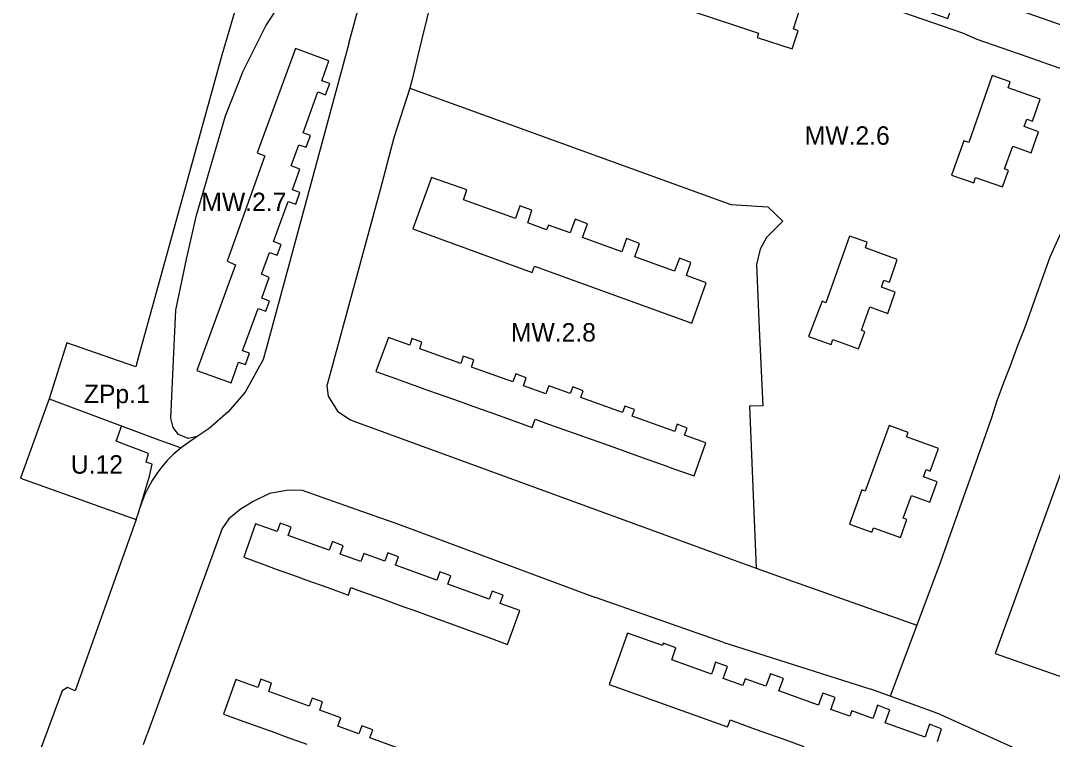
# Model space of a CAD drawing. Extents: x 7428239 to 7429836, y 5549133 to 5550853.
# Drawn here: x 7429036.9 to 7429316.4, y 5550071.7 to 5550266.4 of the extents above; entities that cross this region are included whole.
import ezdxf

# ---------------------------------------------------------------- set-up
doc = ezdxf.new("R2010")
doc.units = 0
for name, color, linetype in [('LIN_linie rozgraniczające', 7, 'Continuous'), ('LIN_nieprzekraczalna linia zabudowy', 7, 'Continuous'), ('LIN_obowiązująca linia zabudowy', 7, 'Continuous'), ('TXT_Oznaczenia Przeznaczenia', 7, 'Continuous')]:
    doc.layers.add(name, color=color, linetype=linetype)

msp = doc.modelspace()

# ---------------------------------------------------------------- linework, layer by layer
at = {"layer": 'LIN_linie rozgraniczające'}
for p, q in [((7429100.94, 5550289.63), (7429091.4, 5550257.09)), ((7429091.4, 5550257.09), (7429068.97, 5550176.06)), ((7429142.32, 5550248.09), (7429137.96, 5550234.67)), ((7429049.35, 5550179.1), (7429044.54, 5550163.96)), ((7429059.24, 5550175.67), (7429049.35, 5550179.1)), ((7429068.02, 5550172.62), (7429059.24, 5550175.67)), ((7429068.97, 5550176.06), (7429068.02, 5550172.62)), ((7429119.83, 5550167.51), (7429120.18, 5550164.65)), ((7429044.54, 5550163.96), (7429043.58, 5550161.27)), ((7429044.54, 5550163.96), (7429073.32, 5550153.2)), ((7429120.18, 5550164.65), (7429122.67, 5550160.56)), ((7429043.58, 5550161.27), (7429036.85, 5550142.43)), ((7429122.67, 5550160.56), (7429126.01, 5550158.31)), ((7429126.01, 5550158.31), (7429127.14, 5550157.89)), ((7429127.14, 5550157.89), (7429230.23, 5550120.21)), ((7429319.78, 5550146.91), (7429300.94, 5550094.93)), ((7429036.85, 5550142.43), (7429064.12, 5550132.66)), ((7429109.41, 5550139.17), (7429104.25, 5550138.25)), ((7429113.23, 5550139.13), (7429109.41, 5550139.17)), ((7429064.12, 5550132.66), (7429068.15, 5550131.21)), ((7429068.15, 5550131.21), (7429068.8, 5550133.04)), ((7429068.8, 5550133.04), (7429069.27, 5550134.6)), ((7429068.15, 5550131.21), (7429051.62, 5550084.84)), ((7429091.47, 5550128.81), (7429085.27, 5550111.76)), ((7429230.23, 5550120.21), (7429236.11, 5550118.05)), ((7429236.11, 5550118.05), (7429244.71, 5550115.01)), ((7429192.45, 5550110.13), (7429183.94, 5550113.3)), ((7429085.27, 5550111.76), (7429071.18, 5550073.05)), ((7429192.59, 5550110.07), (7429192.45, 5550110.13)), ((7429227.15, 5550097.97), (7429192.59, 5550110.07)), ((7429279.68, 5550102.63), (7429272.45, 5550083.41)), ((7429300.94, 5550094.93), (7429354.94, 5550075.82)), ((7429048.11, 5550084.81), (7429042.17, 5550068.75)), ((7429049.58, 5550085.76), (7429048.11, 5550084.81)), ((7429051.62, 5550084.84), (7429049.58, 5550085.76)), ((7429070.18, 5550070.29), (7429071.18, 5550073.05))]:
    msp.add_line(p, q, dxfattribs=at)
for points in [[(7429125.74, 5550260.21), (7429103.38, 5550177.46), (7429102.6, 5550174.57), (7429099.05, 5550168.16), (7429097.72, 5550165.74), (7429093.08, 5550160.45), (7429087.93, 5550155.92), (7429084.71, 5550153.7), (7429082.25, 5550153.23), (7429079.64, 5550154.26), (7429078.14, 5550156.16), (7429077.55, 5550158.71), (7429078.38, 5550176.44), (7429078.93, 5550187.93), (7429081.75, 5550201.8), (7429084.47, 5550213.72), (7429092.38, 5550240.66), (7429097.19, 5550252.76), (7429103.3, 5550265.02), (7429107.16, 5550270.98), (7429113.11, 5550277.33), (7429117.37, 5550280.7), (7429124.29, 5550277.92)], [(7429125.74, 5550260.21), (7429129.91, 5550275.67)], [(7429149.3, 5550275.63), (7429148.13, 5550271.83), (7429145.6, 5550261.47), (7429144.41, 5550256.57), (7429142.93, 5550250.51), (7429142.32, 5550248.09)], [(7429333.65, 5550248.11), (7429309.59, 5550256.62), (7429296, 5550261.33), (7429292.19, 5550263.04), (7429286.94, 5550264.84), (7429266.96, 5550271.69), (7429262.68, 5550273.49), (7429251.91, 5550277.34)], [(7429142.32, 5550248.09), (7429229.26, 5550216.59), (7429239.29, 5550216), (7429243.35, 5550212.06), (7429238.93, 5550207.68), (7429237.26, 5550204.51), (7429236.22, 5550200.36), (7429237.01, 5550182.88), (7429237.96, 5550162.06), (7429234.34, 5550162), (7429236.11, 5550118.05)], [(7429333.65, 5550248.11), (7429331.56, 5550242.76), (7429326.13, 5550228.5), (7429319.2, 5550209.88), (7429315.74, 5550202.36), (7429312.59, 5550193.52), (7429311.01, 5550189.1), (7429308.85, 5550183.07), (7429307.07, 5550178.6), (7429304.85, 5550172.59), (7429303.13, 5550168.26), (7429301.36, 5550163.38), (7429299.9, 5550158.83), (7429293.53, 5550140.62), (7429292.82, 5550138.68), (7429286.13, 5550119.8), (7429279.68, 5550102.63)], [(7429137.96, 5550234.67), (7429134.29, 5550220.55), (7429119.83, 5550167.51)], [(7429081.73, 5550151.64), (7429080.37, 5550150.63), (7429079.91, 5550150.3), (7429078.2, 5550148.82), (7429076.59, 5550147.23), (7429075.1, 5550145.53), (7429073.73, 5550143.73), (7429072.49, 5550141.83), (7429071.39, 5550139.85), (7429070.44, 5550137.8), (7429069.63, 5550135.69), (7429069.27, 5550134.6)], [(7429073.32, 5550153.2), (7429080.37, 5550150.63)], [(7429084.71, 5550153.7), (7429081.73, 5550151.64)], [(7429104.25, 5550138.25), (7429099.89, 5550136.15), (7429096.34, 5550133.94)], [(7429183.94, 5550113.3), (7429139.31, 5550129.91), (7429124.67, 5550135.08), (7429120.07, 5550136.71), (7429113.23, 5550139.13)], [(7429096.34, 5550133.94), (7429093.3, 5550131.44), (7429091.47, 5550128.81)], [(7429244.71, 5550115.01), (7429279.68, 5550102.63)], [(7429227.15, 5550097.97), (7429267.24, 5550085.31)], [(7429286.07, 5550078.43), (7429272.45, 5550083.41), (7429267.24, 5550085.31)], [(7429286.07, 5550078.43), (7429310.06, 5550067.61), (7429344.3, 5550054.83)]]:
    msp.add_lwpolyline(points, dxfattribs=at)
at = {"layer": 'LIN_nieprzekraczalna linia zabudowy'}
for p, q in [((7429071.81, 5550142.95), (7429072.51, 5550146.25)), ((7429068.8, 5550133.04), (7429071.81, 5550142.95)), ((7429068.15, 5550131.21), (7429068.8, 5550133.04))]:
    msp.add_line(p, q, dxfattribs=at)
for points in [[(7429322.96, 5550263.85), (7429328.47, 5550278.88), (7429273.69, 5550298.26), (7429272.97, 5550296.18), (7429261.14, 5550300.29), (7429258.2, 5550291.73), (7429266.2, 5550288.95), (7429264.85, 5550284.79), (7429268.2, 5550283.68), (7429272.92, 5550282.14), (7429271.38, 5550277.36), (7429278.96, 5550274.79), (7429277.67, 5550270.62), (7429288.11, 5550267.04), (7429290.88, 5550275.1), (7429322.96, 5550263.85)], [(7429072.51, 5550146.25), (7429070.87, 5550146.74), (7429071.49, 5550149.14), (7429064.85, 5550151.7), (7429062.75, 5550152.5), (7429063.36, 5550154.22), (7429064.18, 5550156.53)]]:
    msp.add_lwpolyline(points, dxfattribs=at)
at = {"layer": 'LIN_obowiązująca linia zabudowy'}
for points in [[(7429224.72, 5550281.94), (7429221.82, 5550273.34), (7429220.13, 5550273.88), (7429218.56, 5550269.1), (7429236.77, 5550262.99), (7429236.43, 5550261.86), (7429245.9, 5550258.82), (7429247.54, 5550263.69), (7429246.25, 5550264.24), (7429248.69, 5550271.83), (7429244.05, 5550273.33), (7429243.7, 5550272.42), (7429240.33, 5550273.57), (7429241.91, 5550278.48), (7429233.8, 5550281.35), (7429232.53, 5550277.63), (7429230.26, 5550278.37), (7429230.76, 5550280.03)], [(7429111.31, 5550258.91), (7429100.96, 5550230.57), (7429102.98, 5550229.75), (7429092.79, 5550201.21), (7429095.1, 5550200.29), (7429084.61, 5550171.64), (7429093.88, 5550168.31), (7429095.9, 5550173.9), (7429097.75, 5550173.25), (7429098.9, 5550176.28), (7429097.01, 5550176.96), (7429101.17, 5550188.44), (7429103.25, 5550187.68), (7429104.25, 5550190.45), (7429102.18, 5550191.23), (7429104.22, 5550196.86), (7429102.16, 5550197.68), (7429104.31, 5550203.58), (7429106.32, 5550202.85), (7429107.4, 5550205.79), (7429105.4, 5550206.56), (7429109.36, 5550217.45), (7429111.39, 5550216.71), (7429112.52, 5550219.83), (7429110.51, 5550220.6), (7429112.53, 5550226.13), (7429110.19, 5550227.09), (7429112.24, 5550232.81), (7429114.22, 5550232.1), (7429115.37, 5550235.31), (7429113.4, 5550236.03), (7429117.37, 5550247.09), (7429119.5, 5550246.32), (7429120.59, 5550249.36), (7429118.45, 5550250.09), (7429120.4, 5550255.54)], [(7429300.09, 5550251.52), (7429293.75, 5550233.36), (7429292.43, 5550233.86), (7429289.05, 5550224.52), (7429295.09, 5550222.48), (7429295.61, 5550223.89), (7429302.91, 5550221.35), (7429304.54, 5550225.82), (7429303.48, 5550226.22), (7429305.74, 5550232.37), (7429310.71, 5550230.59), (7429312.69, 5550236.28), (7429308.75, 5550237.77), (7429309.47, 5550239.73), (7429311.05, 5550239.15), (7429313.15, 5550245.13), (7429304.48, 5550248.25), (7429305, 5550249.81)], [(7429148.19, 5550223.93), (7429143.1, 5550210.05), (7429175.48, 5550198.2), (7429176.06, 5550199.87), (7429218.68, 5550184.45), (7429222.58, 5550195.37), (7429217.24, 5550197.34), (7429218.49, 5550200.85), (7429215.38, 5550202.05), (7429214.03, 5550198.52), (7429203.31, 5550202.45), (7429204.51, 5550206.04), (7429201.06, 5550207.41), (7429199.76, 5550203.75), (7429189.12, 5550207.66), (7429190.44, 5550211.32), (7429187.13, 5550212.6), (7429185.78, 5550208.89), (7429179.91, 5550211.04), (7429179.38, 5550209.75), (7429174.25, 5550211.6), (7429175.4, 5550215.09), (7429172.14, 5550216.28), (7429170.91, 5550212.81), (7429156.89, 5550217.88), (7429157.77, 5550220.53)], [(7429261.4, 5550207.99), (7429255.02, 5550189.99), (7429254.03, 5550190.39), (7429250.36, 5550180.81), (7429256.45, 5550178.68), (7429256.93, 5550179.99), (7429263.89, 5550177.51), (7429265.59, 5550182.14), (7429264.7, 5550182.53), (7429266.99, 5550188.86), (7429271.84, 5550187.09), (7429273.84, 5550192.82), (7429270.11, 5550194.2), (7429270.76, 5550196.07), (7429272.24, 5550195.52), (7429274.38, 5550201.73), (7429265.78, 5550204.85), (7429266.25, 5550206.36)], [(7429136.49, 5550180.57), (7429133.13, 5550171.37), (7429138.74, 5550169.35), (7429141.67, 5550168.3), (7429147.4, 5550166.24), (7429149.96, 5550165.32), (7429155.64, 5550163.28), (7429161.33, 5550161.24), (7429164.24, 5550160.2), (7429169.73, 5550158.23), (7429175.45, 5550156.18), (7429176.26, 5550158.4), (7429179.85, 5550157.12), (7429185.33, 5550155.17), (7429190.92, 5550153.18), (7429193.75, 5550152.17), (7429199.61, 5550150.08), (7429205.23, 5550148.08), (7429210.96, 5550146.05), (7429213.61, 5550145.1), (7429219.35, 5550143.06), (7429222.49, 5550152.01), (7429216.76, 5550154.09), (7429217.48, 5550156.04), (7429214.78, 5550157.05), (7429214.07, 5550155.07), (7429202.58, 5550159.24), (7429203.17, 5550161.06), (7429200.57, 5550161.97), (7429199.92, 5550160.21), (7429188.64, 5550164.31), (7429189.28, 5550166.12), (7429186.48, 5550167.19), (7429185.79, 5550165.35), (7429180, 5550167.46), (7429179.14, 5550165.32), (7429173.08, 5550167.49), (7429173.87, 5550169.66), (7429171.07, 5550170.73), (7429170.2, 5550168.52), (7429159, 5550172.52), (7429159.68, 5550174.49), (7429156.8, 5550175.54), (7429156.11, 5550173.55), (7429145.02, 5550177.52), (7429145.53, 5550179.34), (7429142.88, 5550180.31), (7429142.29, 5550178.5)], [(7429272.15, 5550156.73), (7429265.73, 5550138.96), (7429264.83, 5550139.28), (7429261.47, 5550129.97), (7429267.51, 5550127.79), (7429267.95, 5550129), (7429275.25, 5550126.37), (7429277.01, 5550131.23), (7429276.02, 5550131.59), (7429278.24, 5550137.73), (7429283.18, 5550135.95), (7429285.18, 5550141.48), (7429281.51, 5550142.81), (7429282.22, 5550144.78), (7429283.33, 5550144.38), (7429285.55, 5550150.52), (7429276.91, 5550153.63), (7429277.35, 5550154.85)], [(7429097.29, 5550121.03), (7429102.76, 5550119.05), (7429105.86, 5550117.92), (7429111.47, 5550115.89), (7429114.12, 5550114.93), (7429119.81, 5550112.87), (7429125.66, 5550110.75), (7429126.36, 5550112.81), (7429129.23, 5550111.77), (7429134.87, 5550109.73), (7429140.44, 5550107.71), (7429143.37, 5550106.65), (7429148.95, 5550104.62), (7429154.51, 5550102.61), (7429160.23, 5550100.53), (7429162.95, 5550099.55), (7429168.81, 5550097.42), (7429172.09, 5550106.6), (7429166.81, 5550108.53), (7429167.63, 5550110.77), (7429164.6, 5550111.87), (7429163.77, 5550109.64), (7429152.57, 5550113.74), (7429153.4, 5550115.98), (7429150.45, 5550117.04), (7429149.59, 5550114.83), (7429138.45, 5550118.9), (7429139.22, 5550121.11), (7429136.39, 5550122.22), (7429135.56, 5550119.95), (7429129.8, 5550122.06), (7429129.02, 5550119.84), (7429123.41, 5550121.86), (7429124.2, 5550124.12), (7429121.35, 5550125.28), (7429120.48, 5550122.91), (7429109.34, 5550126.92), (7429110.13, 5550129.13), (7429107.16, 5550130.22), (7429106.34, 5550128), (7429100.47, 5550130.11)]]:
    msp.add_lwpolyline(points, close=True, dxfattribs=at)
for points in [[(7429285.26, 5550071.08), (7429286.38, 5550074.55), (7429285.38, 5550074.92), (7429283.09, 5550075.75), (7429282.34, 5550073.47), (7429281.94, 5550072.27), (7429271.11, 5550076.15), (7429272.37, 5550079.67), (7429271.29, 5550080.07), (7429269.04, 5550080.9), (7429268.19, 5550078.54), (7429267.76, 5550077.35), (7429262.05, 5550079.39), (7429261.53, 5550077.92), (7429256.35, 5550079.77), (7429257.52, 5550083.05), (7429256.58, 5550083.38), (7429254.24, 5550084.23), (7429253.52, 5550082.3), (7429253.03, 5550080.96), (7429242.34, 5550084.79), (7429243.52, 5550088.15), (7429242.58, 5550088.5), (7429240.05, 5550089.43), (7429239.16, 5550087), (7429238.81, 5550086.06), (7429233.17, 5550088.08), (7429232.53, 5550086.3), (7429227.25, 5550088.19), (7429228.38, 5550091.4), (7429227.14, 5550091.86), (7429225.11, 5550092.63), (7429224.37, 5550090.35), (7429224.04, 5550089.34), (7429213.28, 5550093.19), (7429214.39, 5550096.43), (7429210.96, 5550097.7), (7429210.74, 5550097.08), (7429201.33, 5550100.45), (7429199.24, 5550094.6), (7429198.31, 5550092.02), (7429196.35, 5550086.54), (7429228.4, 5550075.06), (7429228.62, 5550075.66), (7429229.07, 5550076.92), (7429235.13, 5550074.75), (7429237.67, 5550073.84), (7429243.61, 5550071.71), (7429249.1, 5550069.74)], [(7429142.65, 5550068.02), (7429131.51, 5550072.09), (7429132.29, 5550074.24), (7429129.34, 5550075.36), (7429128.51, 5550073.18), (7429122.82, 5550075.26), (7429123.64, 5550077.52), (7429117.92, 5550079.6), (7429118.63, 5550081.81), (7429115.84, 5550082.85), (7429115, 5550080.66), (7429104.07, 5550084.63), (7429104.83, 5550086.89), (7429101.94, 5550087.96), (7429101.15, 5550085.69), (7429095.2, 5550087.85), (7429091.85, 5550078.52), (7429097.37, 5550076.52), (7429100.11, 5550075.53), (7429105.73, 5550073.49), (7429108.53, 5550072.48), (7429114.41, 5550070.35)]]:
    msp.add_lwpolyline(points, dxfattribs=at)

# ---------------------------------------------------------------- texts
at = {"layer": 'TXT_Oznaczenia Przeznaczenia'}
for s, p in [('MW.2.6', (7429249.32, 5550232.79)), ('MW.2.7', (7429085.82, 5550214.8)), ('MW.2.8', (7429169.7, 5550179.46)), ('ZPp.1', (7429053.99, 5550162.78)), ('U.12', (7429050.46, 5550143.67))]:
    msp.add_text(s, height=5, dxfattribs=at).set_placement(p)

doc.saveas('drawing.dxf')
